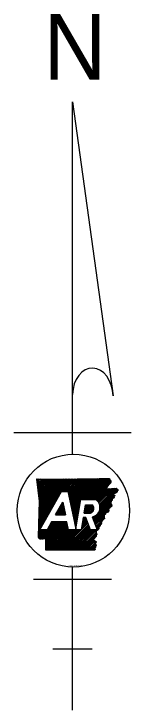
# Model space of a CAD drawing. Extents: x -31696 to 27919, y -8775 to 11152.
# Drawn here: x -1566 to -1039, y -1997 to 1115 of the extents above; entities that cross this region are included whole.
import ezdxf

# ---------------------------------------------------------------- set-up
doc = ezdxf.new("R2010")
doc.units = 0
doc.layers.add('Level 48', color=7, linetype='Continuous')

msp = doc.modelspace()

# ---------------------------------------------------------------- linework, layer by layer
at = {"layer": 'Level 48'}
for p, q in [((-1302.3, 722.8), (-1120.5, -591.3)), ((-1302.3, -853), (-1302.3, 722.8)), ((-1565.5, -755.6), (-1039.2, -755.6)), ((-1462, -965.9), (-1459.8, -963.7)), ((-1461.2, -972.1), (-1452.9, -963.7)), ((-1460.5, -978.3), (-1445.9, -963.7)), ((-1459.7, -984.5), (-1438.9, -963.8)), ((-1458.9, -990.7), (-1432, -963.8)), ((-1458.1, -996.9), (-1425, -963.8)), ((-1457.4, -1003.1), (-1418.1, -963.8)), ((-1456.6, -1009.3), (-1411.1, -963.8)), ((-1455.8, -1015.5), (-1404.1, -963.8)), ((-1455.1, -1021.7), (-1397.2, -963.8)), ((-1454.3, -1027.9), (-1390.2, -963.8)), ((-1453.5, -1034), (-1383.3, -963.8)), ((-1452.7, -1040.2), (-1376.3, -963.8)), ((-1452, -1046.4), (-1369.3, -963.8)), ((-1451.7, -1115.9), (-1299.5, -963.7)), ((-1451.5, -1108.7), (-1306.5, -963.7)), ((-1451.3, -1101.5), (-1313.5, -963.7)), ((-1451.2, -1052.6), (-1362.4, -963.8)), ((-1451, -1094.2), (-1320.5, -963.7)), ((-1450.8, -1087), (-1327.5, -963.7)), ((-1450.5, -1079.8), (-1334.4, -963.7)), ((-1450.4, -1058.8), (-1355.4, -963.8)), ((-1450.3, -1072.6), (-1341.4, -963.7)), ((-1450.1, -1065.4), (-1348.4, -963.8)), ((-1348.3, -1019.4), (-1292.6, -963.6)), ((-1341.3, -1019.4), (-1285.6, -963.6)), ((-1334.4, -1019.4), (-1278.6, -963.6)), ((-1327.4, -1019.4), (-1271.5, -963.5)), ((-1323.1, -1022), (-1264.4, -963.3)), ((-1321.8, -1027.8), (-1257.3, -963.2)), ((-1320.6, -1033.5), (-1250.2, -963.1)), ((-1319.4, -1039.2), (-1243.2, -963)), ((-1318.2, -1045), (-1236.1, -962.9)), ((-1316.9, -1050.7), (-1229, -962.8)), ((-1315.7, -1056.4), (-1221.9, -962.7)), ((-1314.5, -1062.2), (-1214.9, -962.6)), ((-1313.2, -1067.9), (-1207.8, -962.5)), ((-1312, -1073.7), (-1200.7, -962.4)), ((-1310.8, -1079.4), (-1193.6, -962.3)), ((-1309.6, -1085.1), (-1186.6, -962.1)), ((-1308.3, -1090.9), (-1179.5, -962)), ((-1307.1, -1096.6), (-1172.3, -961.8)), ((-1258.7, -1055.2), (-1165.2, -961.7)), ((-1251.7, -1055.2), (-1158.1, -961.5)), ((-1244.8, -1055.2), (-1150.9, -961.3)), ((-1237.8, -1055.2), (-1143.8, -961.2)), ((-1230.8, -1055.2), (-1136.7, -961)), ((-1223.9, -1055.2), (-1135.1, -966.4)), ((-1216.9, -1055.2), (-1131.8, -970)), ((-1210, -1055.2), (-1130.9, -976.1)), ((-1449.7, -1191), (-1352.5, -1019.4)), ((-1352.5, -1019.4), (-1323.6, -1019.4)), ((-1203, -1055.2), (-1146.8, -999)), ((-1196.7, -1055.8), (-1148.1, -1007.3)), ((-1192.9, -1059), (-1140.8, -1006.9)), ((-1189.5, -1062.5), (-1133.5, -1006.5)), ((-1186.4, -1066.5), (-1126.1, -1006.2)), ((-1183.9, -1070.9), (-1118.8, -1005.8)), ((-1181.7, -1075.7), (-1111.4, -1005.4)), ((-1180.1, -1081.1), (-1104.8, -1005.8)), ((-1179.2, -1087.1), (-1101.6, -1009.5)), ((-1104.6, -1019.5), (-1098.3, -1013.2)), ((-1452.2, -1130.3), (-1367.1, -1045.1)), ((-1452, -1123.1), (-1358, -1029.1)), ((-1265, -1055.2), (-1197.5, -1055.2)), ((-1180.6, -1102.5), (-1117.4, -1039.2)), ((-1179.1, -1094), (-1118.2, -1033.1)), ((-1125.2, -1054), (-1116.6, -1045.4)), ((-1452.7, -1144.7), (-1385.3, -1077.3)), ((-1452.5, -1137.5), (-1376.2, -1061.2)), ((-1378.2, -1123.6), (-1346.4, -1067.5)), ((-1377.9, -1123.6), (-1342.1, -1087.8)), ((-1369.5, -1108.4), (-1343.3, -1082.1)), ((-1360.4, -1092.3), (-1344.5, -1076.4)), ((-1351.4, -1076.2), (-1345.7, -1070.6)), ((-1305.9, -1102.3), (-1266.3, -1062.8)), ((-1304.6, -1108.1), (-1267.8, -1071.3)), ((-1303.4, -1113.8), (-1269.3, -1079.7)), ((-1302.2, -1119.6), (-1270.8, -1088.1)), ((-1250.3, -1116), (-1213.7, -1079.4)), ((-1248.9, -1107.7), (-1220.7, -1079.4)), ((-1247.4, -1099.2), (-1227.6, -1079.4)), ((-1246, -1090.8), (-1234.6, -1079.4)), ((-1244.5, -1082.4), (-1241.5, -1079.4)), ((-1244, -1079.4), (-1212.3, -1079.4)), ((-1243.4, -1116), (-1209.8, -1082.5)), ((-1236.4, -1116), (-1207.5, -1087.1)), ((-1209.4, -1145.1), (-1132.1, -1067.9)), ((-1207.5, -1150.2), (-1130.8, -1073.6)), ((-1205.6, -1155.3), (-1129.5, -1079.2)), ((-1203.7, -1160.4), (-1128.2, -1084.9)), ((-1186.7, -1115.5), (-1133.4, -1062.3)), ((-1453.2, -1159.1), (-1403.5, -1109.4)), ((-1452.9, -1151.9), (-1394.4, -1093.3)), ((-1370.9, -1123.6), (-1340.8, -1093.6)), ((-1363.9, -1123.6), (-1339.6, -1099.3)), ((-1357, -1123.6), (-1338.4, -1105.1)), ((-1350, -1123.6), (-1337.1, -1110.8)), ((-1343, -1123.6), (-1335.9, -1116.5)), ((-1301, -1125.3), (-1272.2, -1096.6)), ((-1299.7, -1131), (-1273.7, -1105)), ((-1298.5, -1136.8), (-1275.2, -1113.4)), ((-1250.4, -1116), (-1221.4, -1116)), ((-1229.4, -1116), (-1206.2, -1092.8)), ((-1222.5, -1116), (-1206.8, -1100.3)), ((-1152, -1115.7), (-1142.3, -1105.9)), ((-1453.7, -1173.5), (-1421.6, -1141.5)), ((-1453.4, -1166.3), (-1412.5, -1125.4)), ((-1378.2, -1123.6), (-1334.4, -1123.6)), ((-1336.1, -1123.6), (-1334.7, -1122.3)), ((-1297.3, -1142.5), (-1276.6, -1121.9)), ((-1296.1, -1148.2), (-1278.1, -1130.3)), ((-1294.8, -1154), (-1279.6, -1138.7)), ((-1293.6, -1159.7), (-1281.1, -1147.2)), ((-1259.3, -1167.2), (-1238.5, -1146.4)), ((-1257.8, -1158.8), (-1240.4, -1141.4)), ((-1256.3, -1150.3), (-1242.4, -1136.4)), ((-1254.9, -1141.9), (-1249.4, -1136.4)), ((-1242.2, -1136.4), (-1253.9, -1136.4)), ((-1222.1, -1191), (-1242.2, -1136.4)), ((-1213.7, -1133.5), (-1192.4, -1191)), ((-1213.1, -1135), (-1211, -1132.9)), ((-1211.2, -1140.1), (-1198, -1126.8)), ((-1201.8, -1165.5), (-1160.1, -1123.7)), ((-1200, -1170.6), (-1160.8, -1131.5)), ((-1198.1, -1175.7), (-1161.6, -1139.2)), ((-1454.1, -1187.9), (-1439.8, -1173.6)), ((-1453.9, -1180.7), (-1430.7, -1157.5)), ((-1452.6, -1228.2), (-1379.4, -1155)), ((-1448.5, -1231), (-1372.4, -1155)), ((-1443.5, -1233), (-1365.5, -1155)), ((-1435.2, -1231.7), (-1358.5, -1155)), ((-1428.1, -1231.6), (-1351.5, -1155)), ((-1422.7, -1233.1), (-1344.6, -1155)), ((-1422.4, -1246.8), (-1330.7, -1155)), ((-1422.4, -1239.8), (-1337.6, -1155)), ((-1422.4, -1253.7), (-1327, -1158.3)), ((-1422.4, -1260.6), (-1325.8, -1164)), ((-1422.4, -1267.6), (-1324.5, -1169.8)), ((-1422.4, -1274.5), (-1323.3, -1175.5)), ((-1422.2, -1281.4), (-1322.1, -1181.2)), ((-1395.9, -1155), (-1416.3, -1191)), ((-1408.4, -1177), (-1386.4, -1155)), ((-1399.3, -1161), (-1393.3, -1155)), ((-1327.7, -1155), (-1395.9, -1155)), ((-1352.7, -1281.5), (-1232.9, -1161.7)), ((-1345.7, -1281.5), (-1231, -1166.8)), ((-1338.8, -1281.5), (-1229.1, -1171.9)), ((-1331.8, -1281.5), (-1227.2, -1177)), ((-1324.9, -1281.6), (-1225.4, -1182)), ((-1292.4, -1165.5), (-1282.5, -1155.6)), ((-1291.1, -1171.2), (-1284, -1164)), ((-1289.9, -1176.9), (-1285.5, -1172.5)), ((-1288.7, -1182.7), (-1286.9, -1180.9)), ((-1262.2, -1184.1), (-1234.8, -1156.6)), ((-1260.8, -1175.6), (-1236.6, -1151.5)), ((-1196.2, -1180.7), (-1174.8, -1159.4)), ((-1194.3, -1185.8), (-1177.8, -1169.3)), ((-1455.2, -1223.8), (-1422.4, -1191)), ((-1455.1, -1216.7), (-1429.4, -1191)), ((-1454.9, -1209.5), (-1436.3, -1191)), ((-1454.6, -1202.3), (-1443.3, -1191)), ((-1454.4, -1195.1), (-1448.9, -1189.7)), ((-1416.3, -1191), (-1449.7, -1191)), ((-1415.3, -1281.4), (-1320.8, -1187)), ((-1408.3, -1281.4), (-1317.9, -1191)), ((-1401.4, -1281.4), (-1310.9, -1191)), ((-1394.4, -1281.4), (-1304, -1191)), ((-1387.5, -1281.5), (-1297, -1191)), ((-1380.5, -1281.5), (-1290, -1191)), ((-1373.6, -1281.5), (-1283.1, -1191)), ((-1366.6, -1281.5), (-1276.1, -1191)), ((-1359.6, -1281.5), (-1269.1, -1191)), ((-1263.4, -1191), (-1320, -1191)), ((-1317.9, -1281.6), (-1223.5, -1187.1)), ((-1311, -1281.6), (-1220.4, -1191)), ((-1304, -1281.6), (-1213.4, -1191)), ((-1297.1, -1281.6), (-1206.4, -1191)), ((-1290.1, -1281.6), (-1199.5, -1191)), ((-1283.1, -1281.6), (-1197.2, -1195.6)), ((-1276.2, -1281.6), (-1196.8, -1202.3)), ((-1269.2, -1281.6), (-1196.5, -1208.9)), ((-1192.4, -1191), (-1222.1, -1191)), ((-1262.3, -1281.7), (-1196.2, -1215.6)), ((-1255.3, -1281.7), (-1207.7, -1234)), ((-1248.4, -1281.7), (-1205.5, -1238.8)), ((-1241.4, -1281.7), (-1203.4, -1243.6)), ((-1234.5, -1281.7), (-1201.2, -1248.4)), ((-1227.5, -1281.7), (-1199.1, -1253.3)), ((-1220.6, -1281.7), (-1197.3, -1258.4)), ((-1213.6, -1281.7), (-1200.4, -1268.5)), ((-1206.7, -1281.7), (-1203.6, -1278.7)), ((-1302.3, -1996.7), (-1302.3, -1357.1)), ((-1477.8, -1411.5), (-1126.9, -1411.5)), ((-1390.1, -1723.1), (-1214.6, -1723.1))]:
    msp.add_line(p, q, dxfattribs=at)
for points in [[(-1462.3, -963.8), (-1366.2, -963.8), (-1281.8, -963.6), (-1182.3, -962.1), (-1136.2, -961)], [(-1462.3, -963.7), (-1366.2, -963.8), (-1281.8, -963.6), (-1182.4, -962.1), (-1136.2, -961)], [(-1455.3, -1223.7), (-1450, -1062.5), (-1462.3, -963.7)], [(-1451.7, -1113.1), (-1450, -1062.5), (-1462.3, -963.8)], [(-1323.6, -1019.4), (-1287.9, -1186.4), (-1265, -1055.2)], [(-1106, -1005.2), (-1097.7, -1013.8), (-1118.5, -1030.9), (-1116.2, -1048.1), (-1134, -1059.8), (-1127.9, -1086.3), (-1141.6, -1098.8), (-1142.9, -1112.4), (-1159.5, -1118.4), (-1162.1, -1144), (-1174.1, -1156.8), (-1179.9, -1176.2), (-1197.3, -1192.1), (-1196, -1220.3), (-1207.8, -1233.6), (-1197, -1257.7), (-1204.5, -1281.8)], [(-1150.5, -1007.4), (-1105.4, -1005.1)], [(-1150.5, -1007.4), (-1105.4, -1005.1)], [(-1346.4, -1067.5), (-1334.4, -1123.6)], [(-1250.4, -1116), (-1244, -1079.4)], [(-1455.3, -1223.8), (-1451.7, -1113.1)], [(-1253.9, -1136.4), (-1263.4, -1191)], [(-1320, -1191), (-1327.7, -1155)], [(-1204.5, -1281.8), (-1422.3, -1281.4), (-1422.5, -1233.3)], [(-1204.5, -1281.8), (-1422.3, -1281.4), (-1422.4, -1233.3)]]:
    msp.add_lwpolyline(points, dxfattribs=at)
for centre, major_axis, ratio, start_param, end_param in [((-1211.5, -594.1), (-3.9, 126.3), 0.719778, 4.712385, 7.768526), ((-1222.6, -1090.8), (-43.6, 0), 0.999987, 1.777838, 4.099264), ((-1228.4, -1094.9), (-22.3, 0), 0.999987, 1.887169, 3.90762)]:
    msp.add_ellipse(centre, major_axis=major_axis, ratio=ratio, start_param=start_param, end_param=end_param, dxfattribs=at)
msp.add_ellipse((-1298.3, -1105.1), major_axis=(252.1, 0), ratio=0.999976, dxfattribs=at)
for points in [[(-1136.2, -961), (-1135.9, -963.6), (-1135.1, -965), (-1135, -967.5), (-1134, -968.6), (-1132.2, -969.6), (-1130.8, -971.3), (-1130.4, -973.3), (-1130.8, -975.4), (-1131, -977.8), (-1131.2, -979.8), (-1131.6, -981.6), (-1133, -983.1), (-1134.3, -984.2), (-1135.6, -985.4), (-1136.5, -986.8), (-1138, -988.1), (-1139.6, -989.7), (-1140.9, -990.9), (-1142.1, -992.6), (-1142.7, -994.4), (-1144, -995.8), (-1145.1, -997), (-1146.5, -998.6), (-1147.2, -1000.2), (-1148.6, -1002), (-1148.9, -1003.8), (-1149.8, -1005.2), (-1149.9, -1005.5)], [(-1136.2, -961), (-1135.9, -963.6), (-1135.1, -965), (-1135, -967.5), (-1134, -968.6), (-1132.3, -969.6), (-1130.7, -971.3), (-1130.4, -973.4), (-1130.8, -975.4), (-1130.9, -977.8), (-1131.2, -979.8), (-1131.5, -981.6), (-1133, -983.1), (-1134.3, -984.2), (-1135.6, -985.4), (-1136.5, -986.7), (-1138, -988.2), (-1139.6, -989.7), (-1140.8, -991), (-1142.1, -992.6), (-1142.7, -994.5), (-1144, -995.8), (-1145.1, -997), (-1146.5, -998.6), (-1147.2, -1000.2), (-1148.6, -1002), (-1148.9, -1003.8), (-1149.8, -1005.2), (-1149.8, -1005.5)], [(-1106, -1005.1), (-1105.4, -1005.1), (-1103.4, -1007.2), (-1102.5, -1009), (-1101.2, -1010), (-1099.7, -1010.6), (-1098.6, -1011.9), (-1097.8, -1013.4), (-1098.2, -1014.7), (-1099.9, -1014.9), (-1101.7, -1015.1), (-1103.5, -1015.1), (-1105, -1016.3), (-1103.6, -1017.9), (-1101.9, -1019.4), (-1101.4, -1021), (-1102.4, -1022.5), (-1104.3, -1023.4), (-1106.1, -1024.1), (-1107.8, -1025.5), (-1108.6, -1026.9), (-1110.4, -1027.5), (-1112.3, -1028), (-1113.9, -1028.2), (-1115.8, -1028.5), (-1117.7, -1029.4), (-1118.5, -1031), (-1118.2, -1033.1), (-1118.3, -1035.5), (-1116.4, -1036.2), (-1114.6, -1036.3), (-1112.9, -1037.2), (-1113.1, -1038.5), (-1114.4, -1040.2), (-1115.8, -1041.5), (-1117.3, -1042.1), (-1118.7, -1043.4), (-1118.2, -1044.7), (-1117, -1045.4), (-1116.1, -1046.8), (-1116.2, -1048.1), (-1117.6, -1049), (-1119.2, -1048.6), (-1120.3, -1047.1), (-1121.6, -1046.7), (-1122.8, -1046.1), (-1124.1, -1046.9), (-1124.1, -1048.6), (-1124.5, -1050.4), (-1124.1, -1051.8), (-1123.6, -1053.7), (-1123.7, -1055.1), (-1124.1, -1057.2), (-1125.1, -1059.3), (-1126.3, -1059.9), (-1126.8, -1057.6), (-1127, -1055.8), (-1127.8, -1054.7), (-1128.7, -1054.7), (-1130, -1055.5), (-1131.3, -1056.9), (-1133, -1058.4), (-1134, -1059.9), (-1133.5, -1061.7), (-1132.2, -1062.2), (-1131.2, -1061.9), (-1130.6, -1060.7), (-1129.7, -1060.5), (-1128.7, -1062.4)], [(-1128.7, -1062.4), (-1128.4, -1064), (-1129.4, -1065.9), (-1129.8, -1067.7), (-1129.7, -1069.6), (-1131.6, -1070.6), (-1133.2, -1071.8), (-1132.2, -1073.2), (-1130.4, -1074.5), (-1128.7, -1075.5), (-1127.6, -1076.5), (-1127.3, -1078.9), (-1127, -1080.5), (-1126.4, -1082.7), (-1126.1, -1084.1), (-1127.2, -1085.9), (-1128.4, -1086.3), (-1129.8, -1085.9), (-1131.3, -1085.8), (-1132.5, -1086.9), (-1133.4, -1088.6), (-1134.3, -1090.3), (-1135, -1091.7), (-1135.7, -1093.2), (-1136.9, -1095), (-1138.6, -1095.3), (-1140.5, -1095.8), (-1141.6, -1097.1), (-1141.4, -1099.3), (-1140.3, -1100.8), (-1139.5, -1102.6), (-1138.9, -1104.2), (-1139.2, -1106.2), (-1140, -1107.8), (-1141.1, -1108.6), (-1141.6, -1110.5), (-1142.4, -1112), (-1143.1, -1112.5), (-1144.5, -1112.3), (-1146.1, -1112), (-1147.3, -1112.1), (-1148.6, -1112.8), (-1149.9, -1112.4), (-1151.2, -1110.9), (-1152.2, -1109.9), (-1153.4, -1109.5), (-1154.7, -1110.1), (-1154.9, -1112.1), (-1154.3, -1114.1), (-1153.8, -1116.8), (-1154.3, -1118.5), (-1154.5, -1121.2)], [(-1154.5, -1121.2), (-1156.6, -1122.8), (-1157.5, -1124.5), (-1162.8, -1124), (-1162.6, -1125.8), (-1164.5, -1126.8), (-1166.2, -1128), (-1165.2, -1129.5), (-1163.4, -1130.8), (-1161.7, -1131.8), (-1160.5, -1132.8), (-1160.3, -1135.2), (-1159.9, -1136.8), (-1159.3, -1138.9), (-1159.1, -1140.4), (-1160.2, -1142.1), (-1161.4, -1142.5), (-1162.7, -1142.1), (-1164.3, -1142), (-1165.5, -1143.2), (-1166.4, -1144.8), (-1167.3, -1146.5), (-1168, -1147.9), (-1168.7, -1149.5), (-1169.9, -1151.3), (-1171.5, -1151.6), (-1173.4, -1152), (-1174.6, -1153.3), (-1174.4, -1155.5), (-1173.3, -1157), (-1172.5, -1158.9), (-1171.9, -1160.5), (-1172.1, -1162.5), (-1173, -1164), (-1174.1, -1164.9), (-1174.6, -1166.8), (-1175.3, -1168.2), (-1176, -1168.7), (-1177.5, -1168.5), (-1179, -1168.3), (-1180.3, -1168.4), (-1181.5, -1169), (-1182.8, -1168.6), (-1184.1, -1167.2), (-1185.2, -1166.1), (-1186.4, -1165.7), (-1187.7, -1166.3), (-1187.8, -1168.3), (-1187.2, -1170.3), (-1186.7, -1173.1), (-1187.2, -1174.7), (-1187.4, -1177.5)], [(-1187.4, -1177.5), (-1187.6, -1177.6), (-1188.6, -1178.9), (-1188.1, -1181), (-1185.7, -1181.8), (-1184.7, -1183.8), (-1184.6, -1185.6), (-1185.4, -1188.1), (-1186.5, -1189.2), (-1188.5, -1189.7), (-1190.1, -1190), (-1190.4, -1192.7), (-1191.1, -1194.1), (-1192.3, -1194.5), (-1194.1, -1193.6), (-1195.2, -1193.2), (-1196.5, -1192.6), (-1198.2, -1191.6), (-1199.4, -1191.8), (-1199.1, -1194.4), (-1199, -1194.5), (-1197.5, -1196.5), (-1196.1, -1198), (-1195.5, -1199.8)], [(-1187.4, -1177.5), (-1187.6, -1177.6), (-1188.6, -1178.9), (-1188.1, -1181), (-1185.7, -1181.8), (-1184.7, -1183.8), (-1184.6, -1185.6), (-1185.4, -1188.1), (-1186.5, -1189.2), (-1188.5, -1189.7), (-1190.1, -1190), (-1190.4, -1192.7), (-1191.1, -1194.1), (-1192.3, -1194.5), (-1194.1, -1193.6), (-1195.2, -1193.2), (-1196.5, -1192.6), (-1198.2, -1191.6), (-1199.4, -1191.8), (-1199.1, -1194.4), (-1199, -1194.5), (-1197.5, -1196.5), (-1196.1, -1198), (-1195.5, -1199.8)], [(-1195.5, -1199.8), (-1196, -1201.2), (-1196.7, -1203.6), (-1196.5, -1205.6), (-1195.6, -1207.3), (-1194.2, -1208.3), (-1192.6, -1209.6), (-1192.7, -1211.7), (-1193.7, -1212.5), (-1195.8, -1212), (-1197.4, -1211.2), (-1198.7, -1211.7), (-1200.5, -1212.6), (-1201.9, -1212.8), (-1201.9, -1215.6), (-1200, -1217.6), (-1198.4, -1217.6), (-1196.5, -1217.9), (-1195.9, -1220), (-1197, -1221.8), (-1198.8, -1222.7), (-1201, -1221.6), (-1202.6, -1220.5), (-1204.2, -1219.4), (-1206.2, -1218.9), (-1207.4, -1219.1), (-1207.9, -1221.6), (-1207, -1223.9), (-1205.4, -1225.4), (-1204, -1227.4), (-1204.2, -1228.9), (-1205.3, -1229.3), (-1207.2, -1229.8), (-1208.3, -1230.3), (-1208.6, -1230.8), (-1208, -1232.8), (-1207.5, -1235), (-1207.5, -1236.7), (-1208.2, -1238.2), (-1209.2, -1240.6), (-1209, -1242.1), (-1208.3, -1242.9), (-1207.4, -1242.6), (-1206.2, -1241.8), (-1205.5, -1240.9), (-1204.8, -1239.7), (-1203.6, -1238.7), (-1202.1, -1239.6), (-1201.7, -1241.4), (-1202.6, -1243), (-1203.8, -1243.7), (-1205.3, -1244.3), (-1206.5, -1245.6), (-1206.2, -1247.2), (-1205.3, -1248), (-1203.1, -1247.6), (-1201.6, -1246.9), (-1200.8, -1246.1), (-1199.8, -1245.1), (-1199.3, -1244), (-1198.5, -1243), (-1197.1, -1242.7), (-1196.4, -1243.6), (-1196.7, -1245.6), (-1197.5, -1247.5), (-1198.7, -1249.1), (-1199.9, -1250.2), (-1201.4, -1252.7), (-1201.1, -1254.9), (-1200.5, -1256.8), (-1199.7, -1258.2), (-1198.3, -1257.9), (-1196.7, -1257.7), (-1195.8, -1258.5), (-1195.8, -1260.2), (-1197, -1261.8), (-1198.2, -1263.3), (-1198.8, -1265.4), (-1198.5, -1267), (-1198.5, -1268.3), (-1199, -1269.8), (-1199.8, -1270.6), (-1202.1, -1270.6), (-1204.3, -1270.4), (-1205.6, -1271.1), (-1205.3, -1273.1), (-1204, -1274.6), (-1203.1, -1275.3), (-1201.7, -1277), (-1201.1, -1278.4), (-1201.3, -1279.6), (-1202.1, -1280.6), (-1204.5, -1281.8)], [(-1195.5, -1199.8), (-1196, -1201.2), (-1196.7, -1203.6), (-1196.5, -1205.6), (-1195.6, -1207.3), (-1194.2, -1208.3), (-1192.6, -1209.6), (-1192.7, -1211.7), (-1193.7, -1212.5), (-1195.8, -1212), (-1197.4, -1211.2), (-1198.7, -1211.7), (-1200.5, -1212.6), (-1201.9, -1212.8), (-1201.9, -1215.6), (-1200, -1217.6), (-1198.4, -1217.6), (-1196.5, -1217.9), (-1195.9, -1220), (-1197, -1221.8), (-1198.8, -1222.7), (-1201, -1221.6), (-1202.6, -1220.5), (-1204.2, -1219.4), (-1206.2, -1218.9), (-1207.4, -1219.1), (-1207.9, -1221.6), (-1207, -1223.9), (-1205.4, -1225.4), (-1204, -1227.4), (-1204.2, -1228.9), (-1205.3, -1229.3), (-1207.2, -1229.8), (-1208.3, -1230.3), (-1208.6, -1230.8), (-1208, -1232.8), (-1207.5, -1235), (-1207.5, -1236.7), (-1208.2, -1238.2), (-1209.2, -1240.6), (-1209, -1242.1), (-1208.3, -1242.9), (-1207.4, -1242.6), (-1206.2, -1241.8), (-1205.5, -1240.9), (-1204.8, -1239.7), (-1203.6, -1238.7), (-1202.1, -1239.6), (-1201.7, -1241.4), (-1202.6, -1243), (-1203.8, -1243.7), (-1205.3, -1244.3), (-1206.5, -1245.6), (-1206.2, -1247.2), (-1205.3, -1248), (-1203.1, -1247.6), (-1201.6, -1246.9), (-1200.8, -1246.1), (-1199.8, -1245.1), (-1199.3, -1244), (-1198.5, -1243), (-1197.1, -1242.7), (-1196.4, -1243.6), (-1196.7, -1245.6), (-1197.5, -1247.5), (-1198.7, -1249.1), (-1199.9, -1250.2), (-1201.4, -1252.7), (-1201.1, -1254.9), (-1200.5, -1256.8), (-1199.7, -1258.2), (-1198.3, -1257.9), (-1196.7, -1257.7), (-1195.8, -1258.5), (-1195.8, -1260.2), (-1197, -1261.8), (-1198.2, -1263.3), (-1198.8, -1265.4), (-1198.5, -1267), (-1198.5, -1268.3), (-1199, -1269.8), (-1199.8, -1270.6), (-1202.1, -1270.6), (-1204.3, -1270.4), (-1205.6, -1271.1), (-1205.3, -1273.1), (-1204, -1274.6), (-1203.1, -1275.3), (-1201.7, -1277), (-1201.1, -1278.4), (-1201.3, -1279.6), (-1202.1, -1280.6), (-1204.5, -1281.8)], [(-1422.5, -1233.3), (-1422.2, -1233.4), (-1423.3, -1232.7), (-1424.9, -1231.9), (-1426.6, -1231.8), (-1428.8, -1231.5), (-1430.7, -1231.3), (-1432.6, -1230), (-1434.6, -1231.4), (-1436.8, -1232.3), (-1438.1, -1231.2), (-1439.9, -1231.9), (-1441.1, -1231.6), (-1443.1, -1233), (-1445.1, -1232.5), (-1446.5, -1232.9), (-1448.3, -1232.8), (-1448.7, -1230.8), (-1450.4, -1230.5), (-1451.9, -1229.7), (-1452.9, -1227.6), (-1453.6, -1226), (-1455.3, -1223.7)], [(-1422.4, -1233.3), (-1422.2, -1233.4), (-1423.3, -1232.7), (-1424.9, -1231.9), (-1426.6, -1231.8), (-1428.8, -1231.5), (-1430.7, -1231.3), (-1432.5, -1230), (-1434.6, -1231.3), (-1436.8, -1232.3), (-1438.1, -1231.2), (-1439.8, -1232), (-1441.1, -1231.6), (-1443.1, -1233), (-1445.1, -1232.5), (-1446.5, -1232.9), (-1448.3, -1232.8), (-1448.7, -1230.8), (-1450.4, -1230.5), (-1451.9, -1229.7), (-1452.9, -1227.6), (-1453.6, -1226), (-1455.3, -1223.8)]]:
    msp.add_spline(points, degree=3, dxfattribs=at)

# ---------------------------------------------------------------- texts
for s, height, p in [('N', 293.3, (-1433.1, 822)), ('STS 10-03-17', 7.288, (-1322.4, -1355.1))]:
    msp.add_text(s, height=height, dxfattribs=at).set_placement(p)

doc.saveas('drawing.dxf')
